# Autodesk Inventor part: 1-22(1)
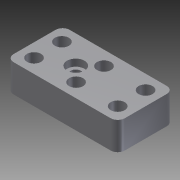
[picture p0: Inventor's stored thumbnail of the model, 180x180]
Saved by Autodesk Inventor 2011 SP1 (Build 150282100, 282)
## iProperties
Created: 2014-02
Part Number: 1-22(1)
Document SubType Name: Modeling
Designer: Administrator
Density: 1 g/cm^3
Author: Administrator
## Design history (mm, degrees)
sketch "草图1"
  geometry: L1 (-15.917, 8.028)-(15.917, 8.028); L2 (15.917, 8.028)-(15.917, -8.028); L3 (15.917, -8.028)-(-15.917, -8.028); L4 (-15.917, -8.028)-(-15.917, 8.028); 3 further points
  constraints: 8 end point, 2 midpoint, 2 parallel, 1 horizontal, 1 horizontal alignment, 1 perpendicular, 1 vertical alignment
extrude "拉伸1" new body sketch "草图1" distance "d0" = 8; taper "d1" = 0 deg
fillet "圆角1" dims "d2" = 2
sketch "草图2"
  geometry: L1 (7.97, -2.047)-(-7.97, -2.047); L2 (-7.97, -2.047)-(-7.97, 1.778); L3 (-7.97, 1.778)-(7.97, 1.778); L4 (7.97, 1.778)-(7.97, -2.047); 4 further points
  constraints: 8 end point, 2 parallel, 2 vertical alignment, 1 horizontal, 1 horizontal alignment, 1 midpoint, 1 perpendicular
extrude "拉伸2" cut sketch "草图2" distance "d3" = 2; taper "d4" = 0 deg
fillet "圆角2" dims "d5" = 1
sketch "草图3"
  geometry: L1 (-7.888, -2.851)-(-7.888, 2.851) reference; L2 (6.888, -3.851)-(-6.888, -3.851) reference; L3 (-6.888, 3.851)-(6.888, 3.851) reference; L4 (7.888, 2.851)-(7.888, -2.851) reference; C1 r 1.5 at (-4.127, 0); 1 further point
  constraints: 1 centre point
  dimensions: "d6" = 3 diameter of C1
extrude "拉伸3" cut sketch "草图3" stored distance "d7" = 2; taper "d8" = 0 deg
hole "Hole1" diameter "d11" = 5; stored, may be unused: countersink angle "d15" = 90 deg, drill point angle "d17" = 0 deg; dims "d9" = 10, "d10" = 10, "d12" = 6, "d13" = 4, "d14" = 2, "d16" = 2
sketch "草图4"
  geometry: C1 r 2 at (11.91, -4.026); C2 r 2 at (0, -4.026); C3 r 2 at (-12.044, -4.026); C4 r 2 at (-12.044, 3.959); C5 r 2 at (0, 3.959); C6 r 2 at (11.91, 3.959); 1 further point
  constraints: 6 centre point
  dimensions: "d18" = 4 diameter of C1; "d19" = 4 diameter of C2; "d20" = 4 diameter of C3; "d21" = 4 diameter of C4; "d22" = 4 diameter of C5; "d23" = 4 diameter of C6
extrude "拉伸4" cut sketch "草图4" distance "d24" = 3; taper "d25" = 0 deg
sketch "草图5"
  geometry: C1 r 2 at (0, 3.959) reference; C2 r 2 at (11.91, -4.026) reference; C3 r 2 at (0, -4.026) reference; C4 r 2 at (-12.044, -4.026) reference; C5 r 2 at (11.91, 3.959) reference; C6 r 2 at (-12.044, 3.959) reference; C7 r 1.5 at (-12.044, 3.959); C8 r 1.5 at (-12.044, -4.026); C9 r 1.5 at (0, -4.026); C10 r 1.5 at (0, 3.959); C11 r 1.5 at (11.91, -4.026); C12 r 1.5 at (11.91, 3.959); 1 further point
  constraints: 6 centre point, 6 coincident
  dimensions: "d26" = 3 diameter of C7; "d27" = 3 diameter of C8; "d28" = 3 diameter of C9; "d29" = 3 diameter of C10; "d30" = 3 diameter of C11; "d31" = 3 diameter of C12
extrude "拉伸5" cut sketch "草图5" stored distance "d32" = 3; taper "d33" = 0 deg
fillet "圆角3" dims "d34" = 1
node "实体1"
